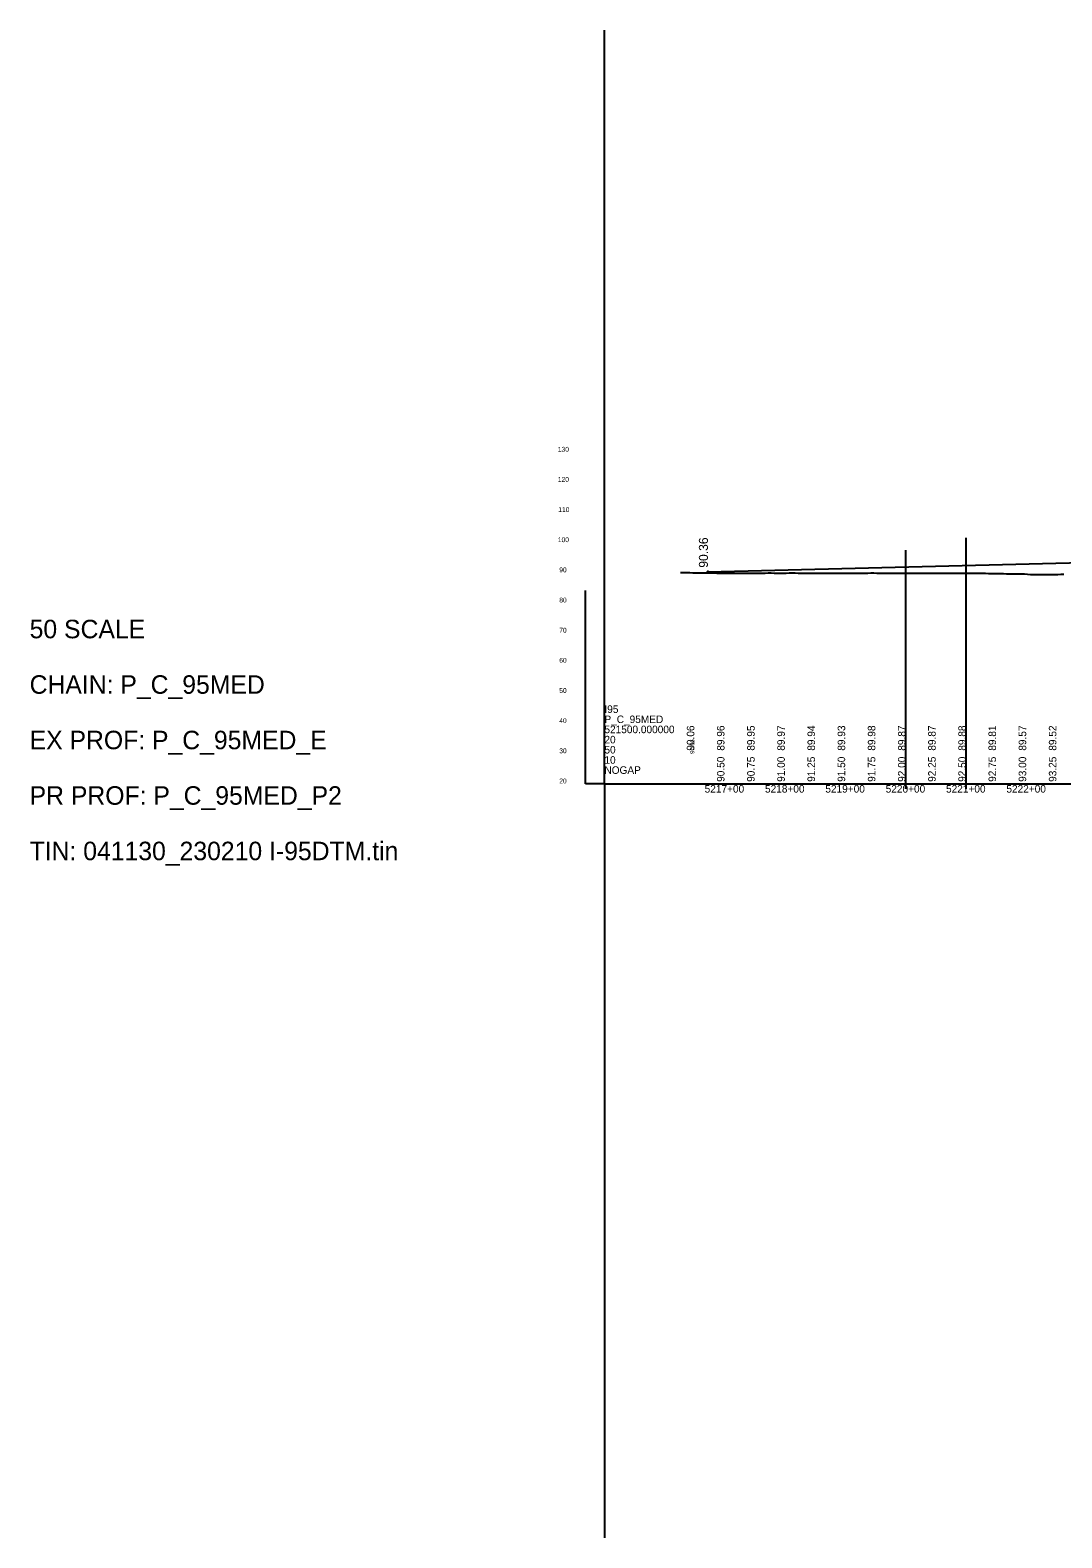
# Model space of a CAD drawing. Extents: x 2121671 to 2169879, y 557274 to 599957.
# Drawn here: x 2150117 to 2151826, y 594457 to 596957 of the extents above; entities that cross this region are included whole.
import ezdxf

# ---------------------------------------------------------------- set-up
doc = ezdxf.new("R2010")
doc.units = 0
for name, color, linetype in [('RD_DDB_ElevTX', 7, 'Continuous'), ('RD_DDB_GradeTX', 7, 'Continuous'), ('RD_DDB_Profile_EX', 7, 'Continuous'), ('RD_DDB_Profile_Lbl', 7, 'Continuous'), ('RD_DDB_Profile_PR', 7, 'Continuous'), ('RD_DDB_StaTX', 7, 'Continuous'), ('RD_DDB_StripGrade', 7, 'Continuous'), ('RD_GPK_Profile_Cell', 7, 'Continuous'), ('RD_HC_Data_Rel', 7, 'Continuous')]:
    doc.layers.add(name, color=color, linetype=linetype)

msp = doc.modelspace()

# ---------------------------------------------------------------- linework, layer by layer
at = {"layer": 'RD_DDB_GradeTX'}
msp.add_circle((2151239.8, 596059.3), 1, dxfattribs=at)
at = {"layer": 'RD_DDB_Profile_EX'}
for points in [[(2151194.5, 596057.9), (2151199.5, 596057.9), (2151204.5, 596057.9), (2151209.5, 596057.9), (2151214.5, 596057.8), (2151219.5, 596057.8), (2151224.5, 596057.7), (2151229.5, 596057.6), (2151234.5, 596057.6), (2151239.5, 596057.5), (2151244.5, 596057.5), (2151249.5, 596057.4), (2151254.5, 596057.3), (2151259.5, 596057.3), (2151264.5, 596057.2), (2151269.5, 596057.3), (2151274.5, 596057.3), (2151279.5, 596057.2), (2151284.5, 596057.2), (2151289.5, 596057.1), (2151294.5, 596057.1), (2151299.5, 596057.1), (2151304.5, 596057.1), (2151309.5, 596057.2), (2151314.5, 596057.2), (2151319.5, 596057.2), (2151324.5, 596057.3), (2151329.5, 596057.3), (2151334.5, 596057.3), (2151339.5, 596057.4), (2151344.5, 596057.4), (2151349.5, 596057.3), (2151354.5, 596057.3), (2151359.5, 596057.3), (2151364.5, 596057.3), (2151369.5, 596057.3), (2151374.5, 596057.4), (2151379.5, 596057.4), (2151384.5, 596057.4), (2151389.5, 596057.3), (2151394.5, 596057.3), (2151399.5, 596057.2), (2151404.5, 596057.2), (2151409.5, 596057.2), (2151414.5, 596057.2), (2151419.5, 596057.2), (2151424.5, 596057.1), (2151429.5, 596057.1), (2151434.5, 596057), (2151439.5, 596057), (2151444.5, 596057), (2151449.5, 596057), (2151454.5, 596057), (2151459.5, 596057), (2151464.5, 596057.1), (2151469.5, 596057.1), (2151474.5, 596057.1), (2151479.5, 596057.1), (2151484.5, 596057.1), (2151489.5, 596057.2), (2151494.5, 596057.2), (2151499.5, 596057.3), (2151504.5, 596057.3), (2151509.5, 596057.4), (2151514.5, 596057.4), (2151519.5, 596057.3), (2151524.5, 596057.3), (2151529.5, 596057.2), (2151534.5, 596057.2), (2151539.5, 596057.1), (2151544.5, 596057.1), (2151549.5, 596057), (2151554.5, 596057), (2151559.5, 596056.9), (2151564.5, 596056.8), (2151569.5, 596056.8), (2151574.5, 596056.8), (2151579.5, 596056.8), (2151584.5, 596056.8), (2151589.5, 596056.8), (2151594.5, 596056.8), (2151599.5, 596056.9), (2151604.5, 596056.9), (2151609.5, 596056.9), (2151614.5, 596056.8), (2151619.5, 596056.8), (2151624.5, 596056.8), (2151629.5, 596056.8), (2151634.5, 596056.8), (2151639.5, 596056.9), (2151644.5, 596056.9), (2151649.5, 596056.9), (2151654.5, 596056.9), (2151659.5, 596056.9), (2151664.5, 596056.9), (2151669.5, 596056.9), (2151674.5, 596056.8), (2151679.5, 596056.8), (2151684.5, 596056.8), (2151689.5, 596056.8), (2151694.5, 596056.8)], [(2151194.5, 596057.9), (2151199.5, 596057.9), (2151204.5, 596057.9), (2151209.5, 596057.9), (2151214.5, 596057.8), (2151219.5, 596057.8), (2151224.5, 596057.7), (2151229.5, 596057.6), (2151234.5, 596057.6), (2151239.5, 596057.5), (2151239.8, 596057.5)], [(2151694.5, 596056.8), (2151699.5, 596056.8), (2151704.5, 596056.7), (2151709.5, 596056.7), (2151714.5, 596056.6), (2151719.5, 596056.5), (2151724.5, 596056.4), (2151729.5, 596056.3), (2151734.5, 596056.1), (2151739.5, 596056), (2151744.5, 596056.2), (2151749.5, 596056.1), (2151754.5, 596056), (2151759.5, 596055.9), (2151764.5, 596055.8), (2151769.5, 596055.2), (2151774.5, 596055), (2151779.5, 596055), (2151784.5, 596055), (2151789.5, 596055), (2151794.5, 596054.9), (2151799.5, 596054.9), (2151804.5, 596054.8), (2151809.5, 596054.9), (2151814.5, 596054.9), (2151819.5, 596055.1), (2151824.5, 596055.2), (2151829.5, 596055.3)]]:
    msp.add_lwpolyline(points, dxfattribs=at)
at = {"layer": 'RD_DDB_Profile_Lbl'}
for p, q in [((2151667.9, 595699.4), (2151667.9, 596115.5)), ((2151567.9, 595699.4), (2151567.9, 596095.2))]:
    msp.add_line(p, q, dxfattribs=at)
at = {"layer": 'RD_DDB_Profile_PR'}
msp.add_line((2151239.8, 596059.3), (2152043.2, 596079.4), dxfattribs=at)
at = {"layer": 'RD_DDB_StripGrade'}
for p, q in [((2151037.1, 595707.5), (2151037.1, 596028.1)), ((2151068.2, 595707.5), (2151037.1, 595707.5))]:
    msp.add_line(p, q, dxfattribs=at)
at = {"layer": 'RD_GPK_Profile_Cell'}
for q in [(2151068.2, 596957.5), (2151068.2, 596957.5), (2158268.2, 595707.5), (2151068.2, 594457.5), (2158268.2, 595707.5), (2151068.2, 594457.5)]:
    msp.add_line((2151068.2, 595707.5), q, dxfattribs=at)

# ---------------------------------------------------------------- texts
at = {"layer": 'RD_DDB_ElevTX'}
for s, p in [('130', (2150991, 596258.5)), ('120', (2150991, 596208.5)), ('110', (2150991.8, 596158.5)), ('100', (2150991, 596108.5)), ('90', (2150993.4, 596058.5)), ('80', (2150993.4, 596008.5)), ('70', (2150993.4, 595958.5)), ('60', (2150993.4, 595908.5)), ('50', (2150993.4, 595858.5)), ('40', (2150993.4, 595808.5)), ('30', (2150993.4, 595758.5)), ('20', (2150993.4, 595708.5))]:
    msp.add_text(s, height=8, dxfattribs=at).set_placement(p)
at = {"layer": 'RD_DDB_Profile_Lbl'}
msp.add_text('90.36', height=15, rotation=90, dxfattribs=at).set_placement((2151239.8, 596066.1))
at = {"layer": 'RD_DDB_StaTX'}
for s, p in [('5217+00', (2151234.3, 595693.2)), ('5218+00', (2151334.3, 595693.2)), ('5219+00', (2151434.3, 595693.2)), ('5220+00', (2151534.3, 595693.2)), ('5221+00', (2151634.3, 595693.2)), ('5222+00', (2151734.3, 595693.2))]:
    msp.add_text(s, height=12.5, dxfattribs=at).set_placement(p)
at = {"layer": 'RD_DDB_StripGrade'}
for s, height, p in [('90.06', 12.5, (2151217.2, 595762.7)), ('89.96', 12.5, (2151267.2, 595762.7)), ('89.95', 12.5, (2151317.2, 595762.7)), ('89.97', 12.5, (2151367.2, 595762.7)), ('89.94', 12.5, (2151417.2, 595762.7)), ('89.93', 12.5, (2151467.2, 595762.7)), ('89.98', 12.5, (2151517.2, 595762.7)), ('89.87', 12.5, (2151567.2, 595762.7)), ('89.87', 12.5, (2151617.2, 595762.7)), ('89.88', 12.5, (2151667.2, 595762.7)), ('89.81', 12.5, (2151717.2, 595762.7)), ('89.57', 12.5, (2151767.2, 595762.7)), ('89.52', 12.5, (2151817.2, 595762.7)), ('90.06', 7, (2151217.2, 595757.5)), ('90.50', 12.5, (2151267.2, 595711)), ('90.75', 12.5, (2151317.2, 595711)), ('91.00', 12.5, (2151367.2, 595711)), ('91.25', 12.5, (2151417.2, 595711)), ('91.50', 12.5, (2151467.2, 595711)), ('91.75', 12.5, (2151517.2, 595711)), ('92.00', 12.5, (2151567.2, 595711)), ('92.25', 12.5, (2151617.2, 595711)), ('92.50', 12.5, (2151667.2, 595711)), ('92.75', 12.5, (2151717.2, 595711)), ('93.00', 12.5, (2151767.2, 595711)), ('93.25', 12.5, (2151817.2, 595711))]:
    msp.add_text(s, height=height, rotation=90, dxfattribs=at).set_placement(p)
at = {"layer": 'RD_GPK_Profile_Cell'}
for s, height, p in [('I95', 12.5, (2151068.2, 595825.3)), ('521500.000000', 12.5, (2151068.2, 595791.7)), ('P_C_95MED', 12.5, (2151068.2, 595808.5)), ('20', 12.5, (2151068.2, 595774.8)), ('50', 12.5, (2151068.2, 595758)), ('10', 12.5, (2151068.2, 595741.1)), ('NOGAP', 12.5, (2151068.2, 595724.3)), ('I95', 0.208, (2151068.2, 595711.8)), ('P_C_95MED', 0.208, (2151068.2, 595711.2)), ('521500.000000', 0.208, (2151068.2, 595710.6)), ('20', 0.208, (2151068.2, 595710)), ('50', 0.208, (2151068.2, 595709.3)), ('10', 0.208, (2151068.2, 595708.7)), ('NOGAP', 0.208, (2151068.2, 595708.1))]:
    msp.add_text(s, height=height, dxfattribs=at).set_placement(p)
at = {"layer": 'RD_HC_Data_Rel'}
for s, height, p in [('50 SCALE', 30.67, (2150115.7, 595949.1)), ('CHAIN: P_C_95MED', 30.668, (2150115.7, 595857.1)), ('EX PROF: P_C_95MED_E', 30.668, (2150115.7, 595765.1)), ('PR PROF: P_C_95MED_P2', 30.668, (2150115.7, 595673.1)), ('TIN: 041130_230210 I-95DTM.tin', 30.668, (2150115.7, 595581.1))]:
    msp.add_text(s, height=height, rotation=360, dxfattribs=at).set_placement(p)

doc.saveas('drawing.dxf')
